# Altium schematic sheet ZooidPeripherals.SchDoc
size A4
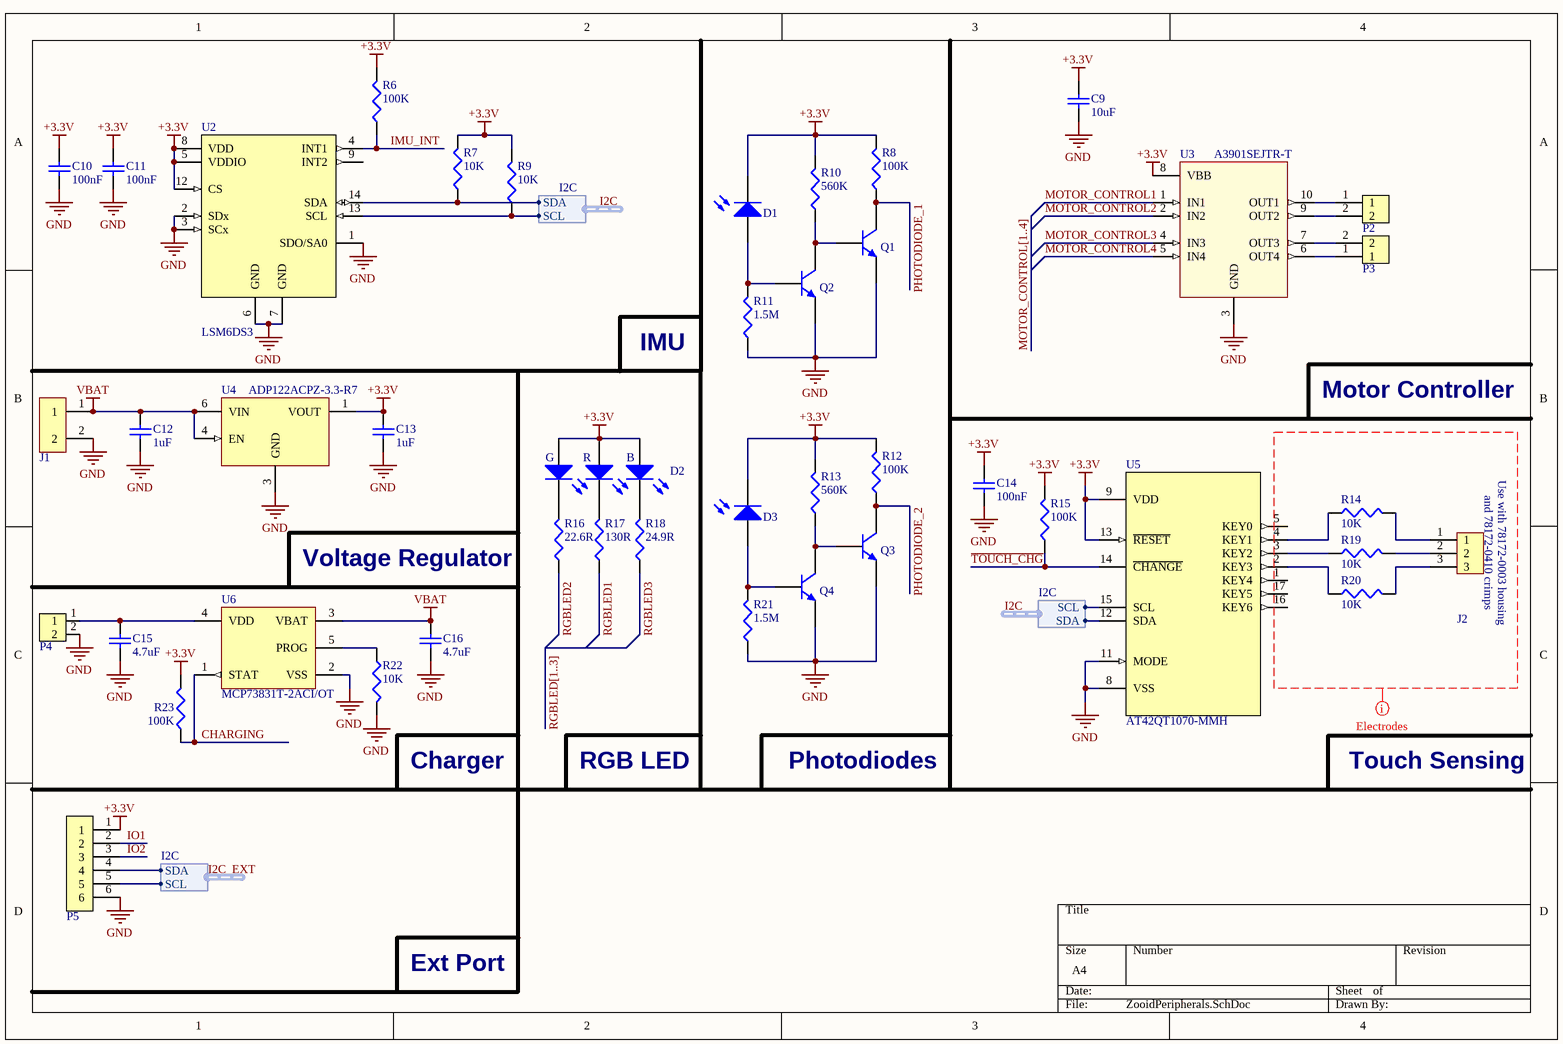
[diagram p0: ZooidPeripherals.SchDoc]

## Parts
C9  10uF  [0603]
C10  100nF  [0402]
C11  100nF  [0402]
C12  1uF  [0603]
C13  1uF  [0603]
C14  100nF  [0402]
C15  4.7uF  [0603]
C16  4.7uF  [0603]
D1  PD15-22C/TR8  [PD15-22C/TR8]  (value not drawn)
D2  SMLVN6RGB1W1  [3.5x2.8 mm 6-SMD]  (value not drawn)
D3  PD15-22C/TR8  [PD15-22C/TR8]  (value not drawn)
J1  78171-0002  [78171-0002]  (value not drawn)
J2  78171-0003  [78171-0003]  (value not drawn)
P2  HEADER 2X1 0.05" UNPOLARIZED  [HEADER 2X1 0.05" - UNPOLARIZED]  (value not drawn)
P3  HEADER 2X1 0.05" UNPOLARIZED  [HEADER 2X1 0.05" - UNPOLARIZED]  (value not drawn)
P4  CHARGING PAD  [Charging Pad]  (value not drawn)
P5  EXTENSION_PORT  [EXTENSION_PORT]  (value not drawn)
Q1  MMBT3904L  [SOT23_L]  (value not drawn)
Q2  MMBT3904L  [SOT23_L]  (value not drawn)
Q3  MMBT3904L  [SOT23_L]  (value not drawn)
Q4  MMBT3904L  [SOT23_L]  (value not drawn)
R6  100K  [0402]
R7  10K  [0402]
R8  100K  [0402]
R9  10K  [0402]
R10  560K  [0402]
R11  1.5M  [0402]
R12  100K  [0402]
R13  560K  [0402]
R14  10K  [0402]
R15  100K  [0402]
R16  22.6R  [0402]
R17  130R  [0402]
R18  24.9R  [0402]
R19  10K  [0402]
R20  10K  [0402]
R21  1.5M  [0402]
R22  10K  [0402]
R23  100K  [0402]
U2  LSM6DS3  [LGA-14 2.5x3x0.86 mm 14L]
U3  A3901SEJTR-T  [DFN50P300X300X75_HS-11N]
U4  ADP122ACPZ-3.3-R7  [LFCSP-6 2.0X2.0X0.55]
U5  AT42QT1070-MMH  [QFN45P300X300X85_HS-21L]
U6  MCP73831T-2ACI/OT  [SOT-23-OT5_L]

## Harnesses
I2C: SDA, SCL

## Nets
+3.3V: C9.2 C10.2 C11.2 C13.2 C14.2 D1.2(K) D2.1(AB) D2.2(AR) D2.3(AG) D3.2(K) P5.1 R6.2 R7.2 R8.2 R9.2 R10.2 R12.2 R13.2 R15.2 R23.2 U2.5(VDDIO) U2.8(VDD) U2.12(CS) U3.8(VBB) U4.1(VOUT) U5.9(VDD) U5.13(~{RESET})
GND: C9.1 C10.1 C11.1 C12.1 C13.1 C14.1 C15.1 C16.1 J1.2 P4.2 P5.6 Q1.2(E) Q2.2(E) Q3.2(E) Q4.2(E) R11.1 R21.1 R22.2 U2.1(SDO/SA0) U2.2(SDx) U2.3(SCx) U2.6(GND) U2.7(GND) U3.3(GND) U3.11(PAD) U4.2(NC) U4.3(GND) U4.5(NC) U4.7(THPAD) U5.8(VSS) U5.11(MODE) U5.21(PAD) U6.2(VSS)
VBAT: C12.2 C16.2 J1.1 U4.4(EN) U4.6(VIN) U6.3(VBAT)
CHARGING: R23.1 U6.1(STAT)
I2C.SCL: R9.1 U2.13(SCL) U5.15(SCL) ; harness I2C.SCL
I2C.SDA: R7.1 U2.14(SDA) U5.12(SDA) ; harness I2C.SDA
I2C_EXT.SCL: P5.5 ; harness I2C.SCL
I2C_EXT.SDA: P5.4 ; harness I2C.SDA
IMU_INT: R6.1 U2.4(INT1)
IO1: P5.2
IO2: P5.3
MOTOR_CONTROL1: U3.1(IN1)
MOTOR_CONTROL2: U3.2(IN2)
MOTOR_CONTROL3: U3.4(IN3)
MOTOR_CONTROL4: U3.5(IN4)
PHOTODIODE_1: Q1.3(C) R8.1
PHOTODIODE_2: Q3.3(C) R12.1
RGBLED1: R17.1
RGBLED2: R16.1
RGBLED3: R18.1
~{TOUCH_CHG}: R15.1 U5.14(~{CHANGE})
NetC15_2: C15.2 P4.1 U6.4(VDD)
NetD1_1: D1.1(A) Q2.1(B) R11.2
NetD2_4: D2.4(KG) R16.2
NetD2_5: D2.5(KR) R17.2
NetD2_6: D2.6(KB) R18.2
NetD3_1: D3.1(A) Q4.1(B) R21.2
NetJ2_1: J2.1 R14.2
NetJ2_2: J2.2 R19.2
NetJ2_3: J2.3 R20.2
NetP2_1: P2.1 U3.10(OUT1)
NetP2_2: P2.2 U3.9(OUT2)
NetP3_1: P3.1 U3.6(OUT4)
NetP3_2: P3.2 U3.7(OUT3)
NetQ1_1: Q1.1(B) Q2.3(C) R10.1
NetQ3_1: Q3.1(B) Q4.3(C) R13.1
NetR14_1: R14.1 U5.4(KEY1)
NetR19_1: R19.1 U5.3(KEY2)
NetR20_1: R20.1 U5.2(KEY3)
NetR22_1: R22.1 U6.5(PROG)

Not connected (* = marked no-connect by the designer): U2 9(INT2) 10(OCS) 11(NC); U5 1(KEY4) 5(KEY0) 6(NC) 7(NC) 10(NC) 16(KEY6) 17(KEY5) 18(NC) 19(NC) 20(NC)

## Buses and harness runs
bus MOTOR_CONTROL[1..4]
bus RGBLED[1..3]

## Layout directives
net class Electrodes: (no net found under the mark)

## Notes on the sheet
- IMU
- Motor Controller
- Voltage Regulator
- Charger
- RGB LED
- Photodiodes
- Touch Sensing
- Ext Port

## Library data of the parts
C9 = 10uF: 10uF 0603 X5R 6.3V ±20%
C10 C11 C14 = 100nF: 100nF 0402 X7R 16V ±10%
C12 C13 = 1uF: 1uF 0603 X5R 10V ±10%
C15 C16 = 4.7uF: 4.7uF 0603 X5R 10V ±10%
D1 D3 = PD15-22C/TR8: Everlight PD15-22C/TR8 Silicon PIN Photodiode
D2 = SMLVN6RGB1W1: ROHM SMLVN6RGB1W1 LED Tri-Color Blue/Green/Red Chip LED 6-Pin 1411 T/RLED Tri-Color Blue/Green/Red Chip LED 6-Pin 1411
J1 = 78171-0002: Molex Pico-EZmate™ Wire-to-Board Header, 2 contacts
J2 = 78171-0003: Molex Pico-EZmate™ Wire-to-Board Header, 3 contacts
Q1-Q4 = MMBT3904L: On Semiconductor MMBT3904L General Purpose Transistor  NPN Silicon
R6 R8 R12 R15 R23 = 100K: 100K 0402 1/16W ±1%
R7 R9 R14 R19 R20 R22 = 10K: 10K 0402 1/16W ±1%
R10 R13 = 560K: 560K 0402 1/16W ±1%
R11 R21 = 1.5M: 1.5M 0402 1/16W ±1%
R16 = 22.6R: 22.6R 0402 1/16W ±0.05R
R17 = 130R: 130R 0402 1/16W ±0.05R
R18 = 24.9R: 24.9R 0402 1/16W ±0.05R
U2 = LSM6DS3: STMicroelectronics iNEMO inertial module:   3D accelerometer and 3D gyroscope
U3 = A3901SEJTR-T: ALLEGRO MICROSYSTEMS - A3901SEJTR-T - IC, MOTOR DRIVER
U4 = ADP122ACPZ-3.3-R7: Analog Devices ADP122ACPZ-3.3-R7 - 5.5 V Input, 300 mA, Low Quiescent  Current, CMOS Linear Regulator
U5 = AT42QT1070-MMH: Atmel Seven-channel QTouch® Touch Sensor IC
U6 = MCP73831T-2ACI/OT: Miniature Single-Cell, Fully Integrated Li-Ion, Li-Polymer Charge Management Controller, 4.2V, 5-Pin SOT-23, Industrial Temperature, Tape and Reel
